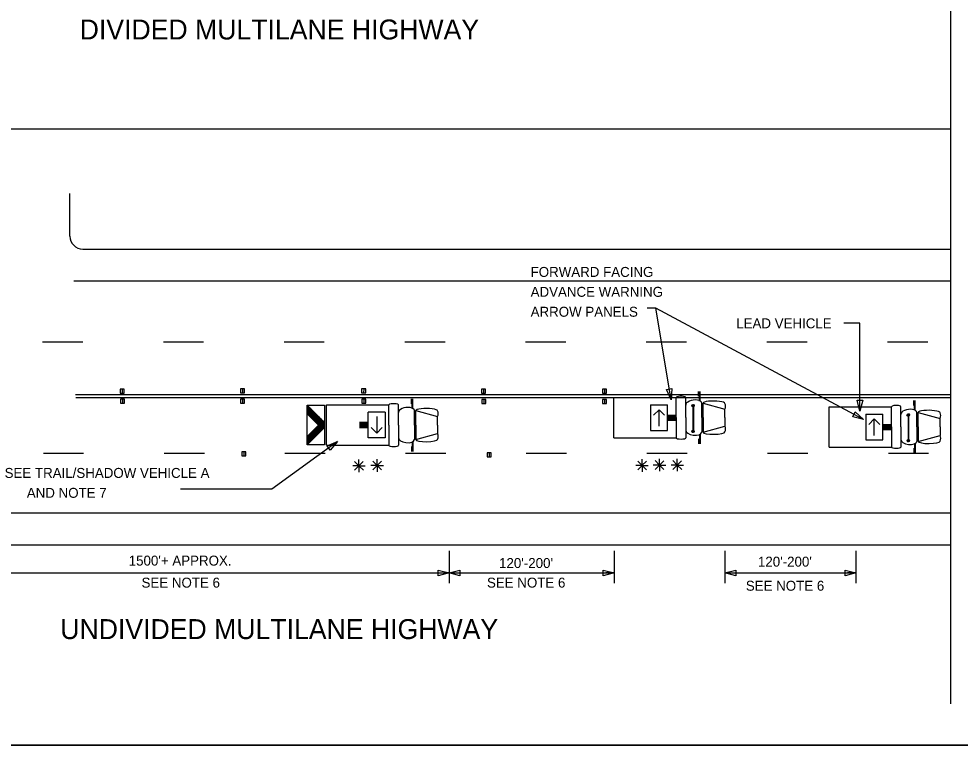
# Model space of a CAD drawing. Extents: x 1374027 to 1374537, y 380415 to 381405.
# Drawn here: x 1374058.8 to 1374115.5, y 381295.2 to 381338.9 of the extents above; entities that cross this region are included whole.
import ezdxf

# ---------------------------------------------------------------- set-up
doc = ezdxf.new("R2010")
doc.units = 0
for name, color, linetype in [('DSN_DRFT_Junk-No-Plot', 7, 'Continuous'), ('Level 1', 7, 'Continuous'), ('Working Level 1', 7, 'Continuous')]:
    doc.layers.add(name, color=color, linetype=linetype)

msp = doc.modelspace()

# ---------------------------------------------------------------- linework, layer by layer
at = {"layer": 'DSN_DRFT_Junk-No-Plot'}
for points in [[(1374027.083, 381405.174), (1374197.083, 381405.174), (1374197.083, 381295.174), (1374027.083, 381295.174)], [(1374027.083, 381405.174), (1374027.083, 381295.174), (1374197.083, 381295.174), (1374197.083, 381405.174)]]:
    msp.add_lwpolyline(points, close=True, dxfattribs=at)
at = {"layer": 'Level 1'}
msp.add_lwpolyline([(1374077.992, 381313.464), (1374074.035, 381310.593), (1374068.546, 381310.593)], dxfattribs=at)
at = {"layer": 'Working Level 1'}
for p, q in [((1374114.956, 381402.674), (1374114.956, 381297.674)), ((1374029.583, 381332.308), (1374114.922, 381332.308)), ((1374061.872, 381325.84), (1374061.872, 381328.41)), ((1374062.648, 381325.064), (1374114.956, 381325.064)), ((1374062.106, 381323.14), (1374114.956, 381323.14)), ((1374109.708, 381314.798), (1374097.192, 381321.499)), ((1374062.205, 381316.292), (1374114.956, 381316.292)), ((1374064.904, 381316.626), (1374064.903, 381316.383)), ((1374064.903, 381316.383), (1374065.146, 381316.383)), ((1374065.146, 381316.626), (1374064.904, 381316.626)), ((1374065.026, 381316.626), (1374065.025, 381316.383)), ((1374065.146, 381316.383), (1374065.146, 381316.626)), ((1374072.148, 381316.644), (1374072.147, 381316.401)), ((1374072.147, 381316.401), (1374072.39, 381316.401)), ((1374072.39, 381316.644), (1374072.148, 381316.644)), ((1374072.27, 381316.644), (1374072.269, 381316.401)), ((1374072.39, 381316.401), (1374072.39, 381316.644)), ((1374079.7, 381316.636), (1374079.457, 381316.636)), ((1374079.457, 381316.636), (1374079.457, 381316.393)), ((1374079.457, 381316.393), (1374079.7, 381316.393)), ((1374079.579, 381316.636), (1374079.578, 381316.393)), ((1374079.7, 381316.393), (1374079.7, 381316.636)), ((1374086.927, 381316.622), (1374086.684, 381316.622)), ((1374086.684, 381316.622), (1374086.684, 381316.379)), ((1374086.684, 381316.379), (1374086.927, 381316.379)), ((1374086.806, 381316.622), (1374086.805, 381316.379)), ((1374086.927, 381316.379), (1374086.927, 381316.622)), ((1374093.968, 381316.622), (1374093.967, 381316.379)), ((1374093.967, 381316.379), (1374094.21, 381316.379)), ((1374094.21, 381316.622), (1374093.968, 381316.622)), ((1374094.09, 381316.622), (1374094.089, 381316.379)), ((1374094.21, 381316.379), (1374094.21, 381316.622)), ((1374099.769, 381316.191), (1374099.769, 381316.488)), ((1374099.816, 381315.905), (1374099.816, 381316.488)), ((1374099.856, 381315.905), (1374099.856, 381316.488)), ((1374103.691, 381316.292), (1374114.956, 381316.292)), ((1374062.239, 381316.124), (1374114.956, 381316.124)), ((1374064.915, 381316.015), (1374064.914, 381315.772)), ((1374064.914, 381315.772), (1374065.157, 381315.772)), ((1374065.157, 381316.015), (1374064.915, 381316.015)), ((1374065.037, 381316.015), (1374065.036, 381315.772)), ((1374065.157, 381315.772), (1374065.157, 381316.015)), ((1374072.151, 381316.026), (1374072.15, 381315.783)), ((1374072.15, 381315.783), (1374072.393, 381315.783)), ((1374072.393, 381316.026), (1374072.151, 381316.026)), ((1374072.272, 381316.026), (1374072.272, 381315.783)), ((1374072.393, 381315.783), (1374072.393, 381316.026)), ((1374076.176, 381315.652), (1374077.212, 381314.617)), ((1374077.346, 381315.67), (1374081.101, 381315.67)), ((1374077.346, 381313.244), (1374077.346, 381315.67)), ((1374079.468, 381316.019), (1374079.467, 381315.776)), ((1374079.467, 381315.776), (1374079.71, 381315.776)), ((1374079.71, 381316.019), (1374079.468, 381316.019)), ((1374079.59, 381316.019), (1374079.589, 381315.776)), ((1374079.71, 381315.776), (1374079.71, 381316.019)), ((1374081.101, 381314.457), (1374081.101, 381315.67)), ((1374081.676, 381314.457), (1374081.676, 381315.67)), ((1374082.452, 381315.742), (1374082.452, 381316.039)), ((1374082.499, 381315.457), (1374082.499, 381316.039)), ((1374082.538, 381315.457), (1374082.538, 381316.039)), ((1374086.695, 381316.005), (1374086.694, 381315.762)), ((1374086.694, 381315.762), (1374086.937, 381315.762)), ((1374086.937, 381316.005), (1374086.695, 381316.005)), ((1374086.817, 381316.005), (1374086.816, 381315.762)), ((1374086.937, 381315.762), (1374086.937, 381316.005)), ((1374093.979, 381316.005), (1374093.978, 381315.762)), ((1374093.978, 381315.762), (1374094.221, 381315.762)), ((1374094.221, 381316.005), (1374093.979, 381316.005)), ((1374094.1, 381316.005), (1374094.1, 381315.762)), ((1374094.221, 381315.762), (1374094.221, 381316.005)), ((1374094.664, 381316.118), (1374098.419, 381316.118)), ((1374094.664, 381313.693), (1374094.664, 381316.118)), ((1374096.87, 381315.682), (1374097.896, 381315.682)), ((1374096.87, 381315.682), (1374096.87, 381314.13)), ((1374097.896, 381314.13), (1374097.896, 381315.682)), ((1374098.419, 381314.906), (1374098.419, 381316.118)), ((1374098.994, 381314.906), (1374098.994, 381316.118)), ((1374099.448, 381315.694), (1374099.448, 381315.694)), ((1374099.958, 381314.906), (1374099.958, 381315.779)), ((1374100.038, 381315.779), (1374101.351, 381315.42)), ((1374100.038, 381314.906), (1374100.038, 381315.779)), ((1374112.738, 381315.634), (1374112.738, 381315.93)), ((1374112.785, 381315.348), (1374112.785, 381315.93)), ((1374112.825, 381315.348), (1374112.825, 381315.93)), ((1374076.176, 381315.134), (1374076.859, 381314.454)), ((1374080.881, 381315.233), (1374079.854, 381315.233)), ((1374079.854, 381313.681), (1374079.854, 381315.233)), ((1374080.881, 381315.233), (1374080.881, 381313.681)), ((1374082.64, 381314.457), (1374082.64, 381315.331)), ((1374082.72, 381315.331), (1374084.033, 381314.972)), ((1374082.72, 381314.457), (1374082.72, 381315.331)), ((1374097.383, 381315.386), (1374097.053, 381315.056)), ((1374097.383, 381314.393), (1374097.383, 381315.386)), ((1374097.383, 381315.386), (1374097.72, 381315.048)), ((1374099.36, 381315.643), (1374099.36, 381315.643)), ((1374099.422, 381315.608), (1374099.422, 381314.103)), ((1374099.426, 381315.608), (1374099.426, 381314.103)), ((1374099.431, 381315.608), (1374099.431, 381314.103)), ((1374099.439, 381315.608), (1374099.439, 381314.103)), ((1374099.45, 381315.608), (1374099.45, 381314.103)), ((1374101.351, 381314.906), (1374101.351, 381315.42)), ((1374107.633, 381315.561), (1374111.388, 381315.561)), ((1374107.633, 381313.135), (1374107.633, 381315.561)), ((1374109.839, 381315.125), (1374110.865, 381315.125)), ((1374109.839, 381315.125), (1374109.839, 381313.572)), ((1374110.865, 381313.572), (1374110.865, 381315.125)), ((1374111.388, 381314.348), (1374111.388, 381315.561)), ((1374111.963, 381314.348), (1374111.963, 381315.561)), ((1374112.329, 381315.086), (1374112.329, 381315.086)), ((1374112.417, 381315.136), (1374112.417, 381315.136)), ((1374112.927, 381314.348), (1374112.927, 381315.222)), ((1374113.007, 381315.222), (1374114.32, 381314.863)), ((1374113.007, 381314.348), (1374113.007, 381315.222)), ((1374079.854, 381314.612), (1374079.332, 381314.612)), ((1374079.854, 381314.534), (1374079.332, 381314.534)), ((1374080.368, 381314.97), (1374080.368, 381313.976)), ((1374084.033, 381314.457), (1374084.033, 381314.972)), ((1374097.896, 381315.061), (1374098.419, 381315.061)), ((1374097.896, 381314.983), (1374098.419, 381314.983)), ((1374097.896, 381314.906), (1374098.419, 381314.906)), ((1374097.896, 381314.828), (1374098.419, 381314.828)), ((1374097.896, 381314.751), (1374098.419, 381314.751)), ((1374098.419, 381314.906), (1374098.419, 381313.693)), ((1374098.994, 381314.906), (1374098.994, 381313.693)), ((1374099.958, 381314.906), (1374099.958, 381314.032)), ((1374100.038, 381314.906), (1374100.038, 381314.032)), ((1374101.351, 381314.906), (1374101.351, 381314.391)), ((1374110.352, 381314.828), (1374110.022, 381314.499)), ((1374110.352, 381313.835), (1374110.352, 381314.828)), ((1374110.352, 381314.828), (1374110.689, 381314.491)), ((1374112.391, 381315.051), (1374112.391, 381313.545)), ((1374112.395, 381315.051), (1374112.395, 381313.545)), ((1374112.4, 381315.051), (1374112.4, 381313.545)), ((1374112.408, 381315.051), (1374112.408, 381313.545)), ((1374112.419, 381315.051), (1374112.419, 381313.545)), ((1374114.32, 381314.348), (1374114.32, 381314.863)), ((1374076.176, 381313.771), (1374076.859, 381314.454)), ((1374076.182, 381313.274), (1374077.207, 381314.299)), ((1374079.854, 381314.457), (1374079.332, 381314.457)), ((1374079.854, 381314.379), (1374079.332, 381314.379)), ((1374079.854, 381314.301), (1374079.332, 381314.301)), ((1374080.368, 381313.976), (1374080.03, 381314.314)), ((1374080.368, 381313.976), (1374080.697, 381314.306)), ((1374081.101, 381314.457), (1374081.101, 381313.245)), ((1374081.676, 381314.457), (1374081.676, 381313.245)), ((1374082.64, 381314.457), (1374082.64, 381313.584)), ((1374082.72, 381314.457), (1374082.72, 381313.584)), ((1374084.033, 381314.457), (1374084.033, 381313.943)), ((1374096.87, 381314.13), (1374097.896, 381314.13)), ((1374099.365, 381314.09), (1374099.365, 381314.09)), ((1374099.452, 381314.141), (1374099.452, 381314.141)), ((1374100.038, 381314.032), (1374101.351, 381314.391)), ((1374110.865, 381314.503), (1374111.388, 381314.503)), ((1374110.865, 381314.426), (1374111.388, 381314.426)), ((1374110.865, 381314.348), (1374111.388, 381314.348)), ((1374110.865, 381314.271), (1374111.388, 381314.271)), ((1374110.865, 381314.193), (1374111.388, 381314.193)), ((1374111.388, 381314.348), (1374111.388, 381313.136)), ((1374111.963, 381314.348), (1374111.963, 381313.136)), ((1374112.927, 381314.348), (1374112.927, 381313.475)), ((1374113.007, 381314.348), (1374113.007, 381313.475)), ((1374114.32, 381314.348), (1374114.32, 381313.834)), ((1374080.881, 381313.681), (1374079.854, 381313.681)), ((1374082.499, 381313.458), (1374082.499, 381312.875)), ((1374082.538, 381313.458), (1374082.538, 381312.875)), ((1374082.72, 381313.584), (1374084.033, 381313.943)), ((1374094.664, 381313.693), (1374098.419, 381313.693)), ((1374099.769, 381313.621), (1374099.769, 381313.324)), ((1374099.816, 381313.906), (1374099.816, 381313.324)), ((1374099.856, 381313.906), (1374099.856, 381313.324)), ((1374109.839, 381313.572), (1374110.865, 381313.572)), ((1374112.334, 381313.532), (1374112.334, 381313.532)), ((1374112.421, 381313.583), (1374112.421, 381313.583)), ((1374113.007, 381313.475), (1374114.32, 381313.834)), ((1374072.233, 381312.853), (1374072.232, 381312.61)), ((1374072.475, 381312.853), (1374072.233, 381312.853)), ((1374072.354, 381312.853), (1374072.354, 381312.61)), ((1374072.475, 381312.61), (1374072.475, 381312.853)), ((1374077.346, 381313.245), (1374081.101, 381313.245)), ((1374082.452, 381313.172), (1374082.452, 381312.875)), ((1374107.633, 381313.136), (1374111.388, 381313.136)), ((1374112.738, 381313.063), (1374112.738, 381312.766)), ((1374112.785, 381313.349), (1374112.785, 381312.766)), ((1374112.825, 381313.349), (1374112.825, 381312.766)), ((1374072.232, 381312.61), (1374072.475, 381312.61)), ((1374079.295, 381312.003), (1374079.029, 381312.269)), ((1374079.288, 381311.998), (1374079.555, 381312.264)), ((1374079.295, 381312.003), (1374079.295, 381312.38)), ((1374080.393, 381312.027), (1374080.127, 381312.293)), ((1374080.386, 381312.022), (1374080.653, 381312.288)), ((1374080.393, 381312.027), (1374080.393, 381312.403)), ((1374087.027, 381312.796), (1374087.026, 381312.553)), ((1374087.026, 381312.553), (1374087.269, 381312.553)), ((1374087.269, 381312.796), (1374087.027, 381312.796)), ((1374087.148, 381312.796), (1374087.148, 381312.553)), ((1374087.269, 381312.553), (1374087.269, 381312.796)), ((1374096.36, 381312.027), (1374096.094, 381312.293)), ((1374096.354, 381312.022), (1374096.62, 381312.288)), ((1374096.36, 381312.027), (1374096.36, 381312.403)), ((1374097.41, 381312.051), (1374097.144, 381312.317)), ((1374097.404, 381312.046), (1374097.67, 381312.312)), ((1374097.41, 381312.051), (1374097.41, 381312.427)), ((1374098.484, 381312.051), (1374098.218, 381312.317)), ((1374098.478, 381312.046), (1374098.744, 381312.312)), ((1374098.484, 381312.051), (1374098.484, 381312.427)), ((1374079.295, 381312.003), (1374078.918, 381312.003)), ((1374079.295, 381312.003), (1374079.029, 381311.737)), ((1374079.295, 381312.003), (1374079.561, 381311.737)), ((1374079.295, 381312.003), (1374079.295, 381311.627)), ((1374079.295, 381312.003), (1374079.671, 381312.003)), ((1374080.393, 381312.027), (1374080.016, 381312.027)), ((1374080.393, 381312.027), (1374080.127, 381311.761)), ((1374080.393, 381312.027), (1374080.659, 381311.761)), ((1374080.393, 381312.027), (1374080.393, 381311.651)), ((1374080.393, 381312.027), (1374080.769, 381312.027)), ((1374096.36, 381312.027), (1374095.984, 381312.027)), ((1374096.36, 381312.027), (1374096.094, 381311.761)), ((1374096.36, 381312.027), (1374096.626, 381311.761)), ((1374096.36, 381312.027), (1374096.36, 381311.651)), ((1374096.36, 381312.027), (1374096.736, 381312.027)), ((1374097.41, 381312.051), (1374097.034, 381312.051)), ((1374097.41, 381312.051), (1374097.144, 381311.785)), ((1374097.41, 381312.051), (1374097.676, 381311.785)), ((1374097.41, 381312.051), (1374097.41, 381311.675)), ((1374097.41, 381312.051), (1374097.786, 381312.051)), ((1374098.484, 381312.051), (1374098.108, 381312.051)), ((1374098.484, 381312.051), (1374098.218, 381311.785)), ((1374098.484, 381312.051), (1374098.75, 381311.785)), ((1374098.484, 381312.051), (1374098.484, 381311.675)), ((1374098.484, 381312.051), (1374098.86, 381312.051)), ((1374034.95, 381309.174), (1374114.956, 381309.174)), ((1374034.95, 381307.236), (1374114.956, 381307.236)), ((1374084.724, 381306.888), (1374084.724, 381304.941)), ((1374094.668, 381306.888), (1374094.668, 381304.941)), ((1374101.354, 381306.888), (1374101.354, 381304.941)), ((1374109.244, 381306.888), (1374109.244, 381304.941)), ((1374053.027, 381305.548), (1374084.724, 381305.548)), ((1374084.724, 381305.548), (1374084.452, 381305.548)), ((1374084.724, 381305.548), (1374085.275, 381305.548)), ((1374084.724, 381305.548), (1374094.668, 381305.548)), ((1374101.354, 381305.548), (1374101.906, 381305.548)), ((1374101.354, 381305.548), (1374109.244, 381305.548))]:
    msp.add_line(p, q, dxfattribs=at)
for points in [[(1374098.119, 381315.988), (1374097.192, 381321.499), (1374096.673, 381321.499)], [(1374109.494, 381315.301), (1374109.494, 381320.589), (1374108.514, 381320.589)], [(1374060.23, 381319.466), (1374062.656, 381319.466)], [(1374067.506, 381319.466), (1374069.931, 381319.466)], [(1374074.781, 381319.466), (1374077.207, 381319.466)], [(1374082.057, 381319.466), (1374084.482, 381319.466)], [(1374089.332, 381319.466), (1374091.758, 381319.466)], [(1374096.608, 381319.466), (1374099.033, 381319.466)], [(1374103.883, 381319.466), (1374106.309, 381319.466)], [(1374111.159, 381319.466), (1374113.584, 381319.466)], [(1374099.366, 381315.661), (1374099.428, 381315.555)], [(1374099.375, 381315.675), (1374099.444, 381315.556)], [(1374099.386, 381315.685), (1374099.458, 381315.561)], [(1374099.398, 381315.693), (1374099.471, 381315.567)], [(1374099.413, 381315.697), (1374099.482, 381315.577)], [(1374099.428, 381315.701), (1374099.492, 381315.59)], [(1374099.446, 381315.698), (1374099.499, 381315.606)], [(1374099.467, 381315.69), (1374099.503, 381315.629)], [(1374076.176, 381315.596), (1374076.805, 381314.507)], [(1374076.176, 381315.503), (1374076.681, 381314.628)], [(1374076.176, 381315.409), (1374076.556, 381314.75)], [(1374076.176, 381315.315), (1374076.431, 381314.872)], [(1374076.176, 381315.221), (1374076.307, 381314.994)], [(1374076.176, 381315.127), (1374076.182, 381315.117)], [(1374076.229, 381315.599), (1374077.062, 381314.155)], [(1374076.356, 381315.471), (1374077.096, 381314.189)], [(1374076.484, 381315.344), (1374077.131, 381314.224)], [(1374076.612, 381315.216), (1374077.165, 381314.258)], [(1374076.74, 381315.088), (1374077.2, 381314.292)], [(1374099.358, 381315.617), (1374099.385, 381315.571)], [(1374099.36, 381315.643), (1374099.409, 381315.558)], [(1374112.329, 381315.086), (1374112.378, 381315.001)], [(1374112.335, 381315.104), (1374112.397, 381314.997)], [(1374112.344, 381315.117), (1374112.413, 381314.999)], [(1374112.355, 381315.127), (1374112.427, 381315.003)], [(1374112.367, 381315.136), (1374112.44, 381315.01)], [(1374112.382, 381315.14), (1374112.451, 381315.02)], [(1374112.397, 381315.143), (1374112.461, 381315.032)], [(1374112.415, 381315.141), (1374112.468, 381315.049)], [(1374112.436, 381315.133), (1374112.472, 381315.072)], [(1374076.868, 381314.96), (1374077.208, 381314.372)], [(1374076.996, 381314.832), (1374077.209, 381314.463)], [(1374077.123, 381314.705), (1374077.211, 381314.554)], [(1374112.327, 381315.059), (1374112.354, 381315.014)], [(1374076.363, 381313.959), (1374076.546, 381313.642)], [(1374076.397, 381313.993), (1374076.58, 381313.676)], [(1374076.432, 381314.027), (1374076.615, 381313.711)], [(1374076.467, 381314.062), (1374076.65, 381313.745)], [(1374076.501, 381314.096), (1374076.684, 381313.779)], [(1374076.535, 381314.131), (1374076.718, 381313.813)], [(1374076.569, 381314.165), (1374076.752, 381313.847)], [(1374076.604, 381314.199), (1374076.787, 381313.881)], [(1374076.638, 381314.234), (1374076.821, 381313.916)], [(1374076.672, 381314.267), (1374076.856, 381313.95)], [(1374076.706, 381314.302), (1374076.89, 381313.984)], [(1374076.741, 381314.336), (1374076.925, 381314.019)], [(1374076.776, 381314.37), (1374076.958, 381314.053)], [(1374076.81, 381314.405), (1374076.993, 381314.087)], [(1374076.844, 381314.439), (1374077.028, 381314.121)], [(1374099.363, 381314.064), (1374099.389, 381314.018)], [(1374099.365, 381314.09), (1374099.413, 381314.005)], [(1374099.371, 381314.108), (1374099.432, 381314.002)], [(1374099.38, 381314.122), (1374099.448, 381314.003)], [(1374099.39, 381314.132), (1374099.462, 381314.008)], [(1374099.402, 381314.14), (1374099.475, 381314.014)], [(1374099.417, 381314.144), (1374099.486, 381314.024)], [(1374099.432, 381314.147), (1374099.496, 381314.037)], [(1374099.45, 381314.145), (1374099.503, 381314.053)], [(1374099.472, 381314.137), (1374099.507, 381314.076)], [(1374076.176, 381313.721), (1374076.34, 381313.437)], [(1374076.176, 381313.627), (1374076.306, 381313.403)], [(1374076.176, 381313.533), (1374076.271, 381313.368)], [(1374076.176, 381313.44), (1374076.237, 381313.334)], [(1374076.192, 381313.787), (1374076.374, 381313.472)], [(1374076.226, 381313.822), (1374076.409, 381313.505)], [(1374076.26, 381313.856), (1374076.443, 381313.54)], [(1374076.295, 381313.891), (1374076.478, 381313.573)], [(1374076.329, 381313.925), (1374076.512, 381313.608)], [(1374112.332, 381313.506), (1374112.358, 381313.46)], [(1374112.334, 381313.532), (1374112.382, 381313.448)], [(1374112.34, 381313.551), (1374112.401, 381313.444)], [(1374112.349, 381313.564), (1374112.417, 381313.446)], [(1374112.359, 381313.574), (1374112.431, 381313.45)], [(1374112.371, 381313.582), (1374112.444, 381313.457)], [(1374112.386, 381313.586), (1374112.455, 381313.466)], [(1374112.401, 381313.59), (1374112.465, 381313.479)], [(1374112.419, 381313.588), (1374112.472, 381313.495)], [(1374112.441, 381313.58), (1374112.476, 381313.518)], [(1374076.176, 381313.346), (1374076.202, 381313.3)], [(1374060.274, 381312.768), (1374062.699, 381312.768)], [(1374067.549, 381312.768), (1374069.975, 381312.768)], [(1374074.825, 381312.768), (1374077.25, 381312.768)], [(1374082.1, 381312.768), (1374084.526, 381312.768)], [(1374089.376, 381312.768), (1374091.801, 381312.768)], [(1374096.651, 381312.768), (1374099.077, 381312.768)], [(1374103.927, 381312.768), (1374106.352, 381312.768)], [(1374111.202, 381312.768), (1374113.628, 381312.768)], [(1374094.668, 381305.548), (1374094.166, 381305.548), (1374094.166, 381305.512)], [(1374109.244, 381305.548), (1374108.741, 381305.548), (1374108.741, 381305.512)]]:
    msp.add_lwpolyline(points, dxfattribs=at)
for points in [[(1374098.151, 381316.657), (1374098.119, 381315.988), (1374097.832, 381316.593)], [(1374077.215, 381313.274), (1374076.176, 381313.274), (1374076.176, 381315.652), (1374077.215, 381315.652)], [(1374109.657, 381315.951), (1374109.494, 381315.301), (1374109.332, 381315.951)], [(1374109.212, 381315.248), (1374109.708, 381314.798), (1374109.058, 381314.961)], [(1374077.37, 381313.214), (1374077.992, 381313.464), (1374077.561, 381312.951)], [(1374084.074, 381305.71), (1374084.724, 381305.548), (1374084.074, 381305.385)], [(1374085.374, 381305.385), (1374084.724, 381305.548), (1374085.374, 381305.71)], [(1374094.018, 381305.71), (1374094.668, 381305.548), (1374094.018, 381305.385)], [(1374102.004, 381305.385), (1374101.354, 381305.548), (1374102.004, 381305.71)], [(1374108.594, 381305.71), (1374109.244, 381305.548), (1374108.594, 381305.385)]]:
    msp.add_lwpolyline(points, close=True, dxfattribs=at)
for centre in [(1374099.43, 381315.628), (1374112.399, 381315.07), (1374099.434, 381314.075), (1374112.404, 381313.517)]:
    msp.add_circle(centre, 0.0728, dxfattribs=at)
for centre, radius, start, end in [((1374062.648, 381325.84), 0.776, 180, 270), ((1374101.029, 381315.592), 0.364, 331.8801, 28.1199), ((1374083.711, 381315.144), 0.364, 331.8801, 28.1199), ((1374113.998, 381315.034), 0.364, 331.8801, 28.1199), ((1374101.029, 381314.22), 0.364, 331.8801, 28.1199), ((1374083.711, 381313.771), 0.364, 331.8801, 28.1199), ((1374113.998, 381313.662), 0.364, 331.8801, 28.1199)]:
    msp.add_arc(centre, radius, start, end, dxfattribs=at)
for centre, major_axis, ratio, start_param, end_param in [((1374081.388, 381315.67), (0.288, 0), 0.269913, 0, 3.141593), ((1374098.706, 381316.118), (0.288, 0), 0.269913, 0, 3.141593), ((1374099.476, 381315.72), (0.482, 0.06), 0.503092, 0, 3.141593), ((1374100.694, 381315.772), (0.656, -0.008), 0.2034, 0, 3.141593), ((1374082.158, 381315.271), (0.482, 0.06), 0.503092, 0, 3.141593), ((1374083.376, 381315.323), (0.656, -0.008), 0.2034, 0, 3.141593), ((1374111.676, 381315.561), (0.288, 0), 0.269913, 0, 3.141593), ((1374112.445, 381315.162), (0.482, 0.06), 0.503092, 0, 3.141593), ((1374113.663, 381315.214), (0.656, -0.008), 0.2034, 0, 3.141593), ((1374099.476, 381314.092), (0.482, -0.06), 0.503092, 3.141593, 6.283185), ((1374100.694, 381314.04), (0.656, 0.008), 0.2034, 3.141593, 6.283185), ((1374082.158, 381313.643), (0.482, -0.06), 0.503092, 3.141593, 6.283185), ((1374083.376, 381313.591), (0.656, 0.008), 0.2034, 3.141593, 6.283185), ((1374098.706, 381313.693), (0.288, 0), 0.269913, 3.141593, 6.283185), ((1374112.445, 381313.534), (0.482, -0.06), 0.503092, 3.141593, 6.283185), ((1374113.663, 381313.482), (0.656, 0.008), 0.2034, 3.141593, 6.283185), ((1374081.388, 381313.245), (0.288, 0), 0.269913, 3.141593, 6.283185), ((1374111.676, 381313.136), (0.288, 0), 0.269913, 3.141593, 6.283185)]:
    msp.add_ellipse(centre, major_axis=major_axis, ratio=ratio, start_param=start_param, end_param=end_param, dxfattribs=at)

# ---------------------------------------------------------------- texts
for s, p in [('DIVIDED MULTILANE HIGHWAY', (1374062.461, 381337.692)), ('UNDIVIDED MULTILANE HIGHWAY', (1374061.292, 381301.566))]:
    msp.add_text(s, height=1.2, rotation=0, dxfattribs=at).set_placement(p)
for s, p in [('FORWARD FACING', (1374089.642, 381323.386)), ('ADVANCE WARNING ', (1374089.642, 381322.186)), ('ARROW PANELS', (1374089.642, 381320.986)), ('LEAD VEHICLE', (1374102.034, 381320.289)), ('SEE TRAIL/SHADOW VEHICLE A', (1374057.937, 381311.276)), ('      AND NOTE 7', (1374057.937, 381310.076)), ("1500'+ APPROX.", (1374065.417, 381305.993)), ("120'-200'", (1374087.74, 381305.847)), ("120'-200'", (1374103.343, 381305.93)), ('SEE NOTE 6', (1374066.19, 381304.666)), ('SEE NOTE 6', (1374087.01, 381304.666)), ('SEE NOTE 6', (1374102.613, 381304.478))]:
    msp.add_text(s, height=0.6, dxfattribs=at).set_placement(p)

doc.saveas('drawing.dxf')
